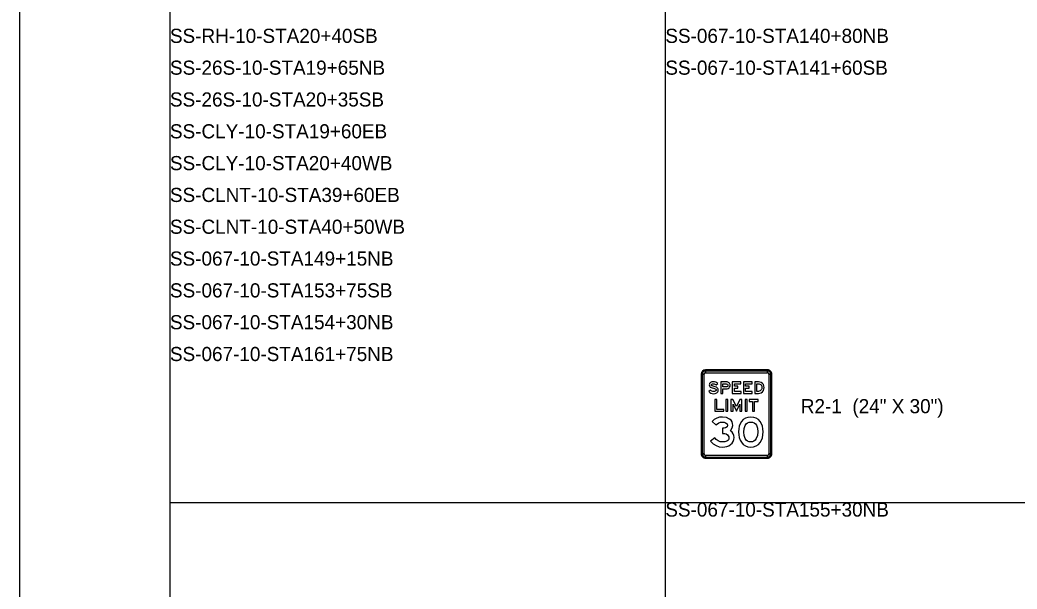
# Model space of a CAD drawing. Extents: x 1001568 to 1002149, y 1840825 to 1841423.
# Drawn here: x 1001886.41 to 1001914.59, y 1841079.02 to 1841095.12 of the extents above; entities that cross this region are included whole.
import ezdxf

# ---------------------------------------------------------------- set-up
doc = ezdxf.new("R2010")
doc.units = 0
for name, color, linetype in [('40', 7, 'Continuous'), ('R_No Plot', 7, 'Continuous'), ('SIGNS', 7, 'Continuous')]:
    doc.layers.add(name, color=color, linetype=linetype)

msp = doc.modelspace()

# ---------------------------------------------------------------- linework, layer by layer
at = {"layer": 'R_No Plot'}
for p, q in [((1001890.65, 1841110.667), (1001890.65, 1841048.127)), ((1001904.65, 1841110.667), (1001904.65, 1841048.127)), ((1001890.65, 1841081.469), (1001982.133, 1841081.469))]:
    msp.add_line(p, q, dxfattribs=at)
msp.add_lwpolyline([(1001886.411, 1841110.667), (1001964.232, 1841110.667), (1001964.232, 1841107.694), (1001968.454, 1841107.694), (1001968.454, 1841106.882), (1001982.133, 1841106.882), (1001982.133, 1841048.127), (1001886.411, 1841048.127)], close=True, dxfattribs=at)
at = {"layer": 'SIGNS'}
for p, q in [((1001905.662, 1841085.094), (1001905.662, 1841082.844)), ((1001905.693, 1841085.094), (1001905.745, 1841085.094)), ((1001907.537, 1841085.219), (1001905.787, 1841085.219)), ((1001905.787, 1841085.136), (1001905.787, 1841085.188)), ((1001907.537, 1841085.188), (1001907.537, 1841085.136)), ((1001907.578, 1841085.094), (1001907.63, 1841085.094)), ((1001907.662, 1841082.844), (1001907.662, 1841085.094)), ((1001905.745, 1841082.844), (1001905.693, 1841082.844)), ((1001905.787, 1841082.75), (1001905.787, 1841082.802)), ((1001905.787, 1841082.719), (1001907.537, 1841082.719)), ((1001907.537, 1841082.802), (1001907.537, 1841082.75)), ((1001907.63, 1841082.844), (1001907.578, 1841082.844))]:
    msp.add_line(p, q, dxfattribs=at)
for points in [[(1001905.693, 1841085.094), (1001905.693, 1841082.844), (1001905.745, 1841082.844), (1001905.745, 1841085.094), (1001905.693, 1841085.094), (1001905.693, 1841085.094)], [(1001907.537, 1841085.188), (1001905.787, 1841085.188), (1001905.787, 1841085.136), (1001907.537, 1841085.136), (1001907.537, 1841085.188), (1001907.537, 1841085.188)], [(1001907.63, 1841082.844), (1001907.63, 1841085.094), (1001907.578, 1841085.094), (1001907.578, 1841082.844), (1001907.63, 1841082.844), (1001907.63, 1841082.844)], [(1001905.878, 1841084.612), (1001905.907, 1841084.583), (1001905.939, 1841084.562), (1001905.975, 1841084.55), (1001906.015, 1841084.546), (1001906.061, 1841084.552), (1001906.102, 1841084.57), (1001906.121, 1841084.585), (1001906.134, 1841084.602), (1001906.142, 1841084.622), (1001906.145, 1841084.644), (1001906.142, 1841084.672), (1001906.133, 1841084.695), (1001906.117, 1841084.715), (1001906.095, 1841084.73), (1001906.063, 1841084.742), (1001906.002, 1841084.758), (1001905.98, 1841084.765), (1001905.965, 1841084.773), (1001905.955, 1841084.782), (1001905.952, 1841084.794), (1001905.955, 1841084.808), (1001905.966, 1841084.819), (1001905.983, 1841084.825), (1001906.007, 1841084.828), (1001906.029, 1841084.826), (1001906.05, 1841084.82), (1001906.069, 1841084.809), (1001906.086, 1841084.795), (1001906.13, 1841084.835), (1001906.104, 1841084.857), (1001906.076, 1841084.873), (1001906.044, 1841084.883), (1001906.009, 1841084.886), (1001905.966, 1841084.88), (1001905.93, 1841084.864), (1001905.914, 1841084.85), (1001905.902, 1841084.834), (1001905.895, 1841084.815), (1001905.893, 1841084.794), (1001905.896, 1841084.77), (1001905.905, 1841084.75), (1001905.921, 1841084.732), (1001905.943, 1841084.719), (1001906.036, 1841084.692), (1001906.058, 1841084.684), (1001906.073, 1841084.674), (1001906.083, 1841084.663), (1001906.086, 1841084.651), (1001906.084, 1841084.64), (1001906.079, 1841084.631), (1001906.071, 1841084.623), (1001906.06, 1841084.616), (1001906.038, 1841084.609), (1001906.014, 1841084.607), (1001905.988, 1841084.61), (1001905.965, 1841084.618), (1001905.944, 1841084.631), (1001905.926, 1841084.65)], [(1001906.542, 1841084.552), (1001906.789, 1841084.552), (1001906.789, 1841084.61), (1001906.602, 1841084.61), (1001906.602, 1841084.7), (1001906.701, 1841084.7), (1001906.701, 1841084.758), (1001906.602, 1841084.758), (1001906.602, 1841084.822), (1001906.783, 1841084.822), (1001906.783, 1841084.879), (1001906.542, 1841084.879)], [(1001906.858, 1841084.552), (1001907.106, 1841084.552), (1001907.106, 1841084.61), (1001906.918, 1841084.61), (1001906.918, 1841084.7), (1001907.017, 1841084.7), (1001907.017, 1841084.758), (1001906.918, 1841084.758), (1001906.918, 1841084.822), (1001907.1, 1841084.822), (1001907.1, 1841084.879), (1001906.858, 1841084.879)], [(1001906.052, 1841084.052), (1001906.299, 1841084.052), (1001906.299, 1841084.102), (1001906.11, 1841084.102), (1001906.11, 1841084.379), (1001906.052, 1841084.379)], [(1001906.358, 1841084.052), (1001906.418, 1841084.052), (1001906.418, 1841084.379), (1001906.358, 1841084.379)], [(1001906.505, 1841084.052), (1001906.563, 1841084.052), (1001906.563, 1841084.254), (1001906.659, 1841084.052), (1001906.757, 1841084.254), (1001906.757, 1841084.052), (1001906.815, 1841084.052), (1001906.815, 1841084.379), (1001906.757, 1841084.379), (1001906.659, 1841084.187), (1001906.562, 1841084.379), (1001906.505, 1841084.379)], [(1001906.905, 1841084.052), (1001906.964, 1841084.052), (1001906.964, 1841084.379), (1001906.905, 1841084.379)], [(1001907.116, 1841084.052), (1001907.174, 1841084.052), (1001907.174, 1841084.324), (1001907.269, 1841084.324), (1001907.269, 1841084.379), (1001907.022, 1841084.379), (1001907.022, 1841084.324), (1001907.116, 1841084.324)], [(1001905.928, 1841083.206), (1001906.002, 1841083.131), (1001906.084, 1841083.079), (1001906.172, 1841083.047), (1001906.268, 1841083.036), (1001906.33, 1841083.041), (1001906.388, 1841083.054), (1001906.441, 1841083.075), (1001906.491, 1841083.106), (1001906.537, 1841083.148), (1001906.57, 1841083.195), (1001906.589, 1841083.248), (1001906.596, 1841083.308), (1001906.589, 1841083.359), (1001906.57, 1841083.409), (1001906.537, 1841083.456), (1001906.491, 1841083.5), (1001906.541, 1841083.577), (1001906.558, 1841083.651), (1001906.552, 1841083.704), (1001906.535, 1841083.752), (1001906.506, 1841083.794), (1001906.466, 1841083.829), (1001906.375, 1841083.871), (1001906.265, 1841083.886), (1001906.181, 1841083.878), (1001906.103, 1841083.855), (1001906.032, 1841083.816), (1001905.969, 1841083.762), (1001906.079, 1841083.662), (1001906.12, 1841083.698), (1001906.164, 1841083.723), (1001906.211, 1841083.739), (1001906.262, 1841083.744), (1001906.311, 1841083.739), (1001906.354, 1841083.725), (1001906.394, 1841083.696), (1001906.407, 1841083.655), (1001906.394, 1841083.612), (1001906.355, 1841083.584), (1001906.312, 1841083.573), (1001906.262, 1841083.572), (1001906.262, 1841083.421), (1001906.283, 1841083.421), (1001906.332, 1841083.418), (1001906.373, 1841083.407), (1001906.406, 1841083.387), (1001906.43, 1841083.358), (1001906.443, 1841083.328), (1001906.448, 1841083.297), (1001906.444, 1841083.267), (1001906.432, 1841083.242), (1001906.412, 1841083.22), (1001906.385, 1841083.203), (1001906.331, 1841083.186), (1001906.266, 1841083.181), (1001906.203, 1841083.188), (1001906.143, 1841083.21), (1001906.089, 1841083.247), (1001906.048, 1841083.296)], [(1001905.787, 1841082.75), (1001907.537, 1841082.75), (1001907.537, 1841082.802), (1001905.787, 1841082.802), (1001905.787, 1841082.75), (1001905.787, 1841082.75)]]:
    msp.add_lwpolyline(points, close=True, dxfattribs=at)
for points in [[(1001906.215, 1841084.552), (1001906.273, 1841084.552), (1001906.273, 1841084.683), (1001906.368, 1841084.683), (1001906.4, 1841084.686), (1001906.428, 1841084.695), (1001906.45, 1841084.71), (1001906.468, 1841084.732), (1001906.478, 1841084.756), (1001906.482, 1841084.781), (1001906.48, 1841084.802), (1001906.474, 1841084.82), (1001906.465, 1841084.837), (1001906.451, 1841084.852), (1001906.435, 1841084.864), (1001906.417, 1841084.872), (1001906.397, 1841084.878), (1001906.375, 1841084.879), (1001906.215, 1841084.879), (1001906.215, 1841084.552)], [(1001906.273, 1841084.738), (1001906.273, 1841084.822), (1001906.37, 1841084.822), (1001906.389, 1841084.819), (1001906.405, 1841084.811), (1001906.416, 1841084.797), (1001906.42, 1841084.779), (1001906.417, 1841084.763), (1001906.406, 1841084.75), (1001906.391, 1841084.741), (1001906.373, 1841084.738), (1001906.273, 1841084.738)], [(1001907.175, 1841084.552), (1001907.282, 1841084.552), (1001907.323, 1841084.558), (1001907.361, 1841084.573), (1001907.396, 1841084.599), (1001907.422, 1841084.632), (1001907.437, 1841084.671), (1001907.442, 1841084.717), (1001907.437, 1841084.763), (1001907.422, 1841084.802), (1001907.397, 1841084.833), (1001907.362, 1841084.859), (1001907.324, 1841084.874), (1001907.286, 1841084.879), (1001907.175, 1841084.879), (1001907.175, 1841084.552)], [(1001907.233, 1841084.61), (1001907.233, 1841084.823), (1001907.28, 1841084.823), (1001907.302, 1841084.822), (1001907.321, 1841084.816), (1001907.339, 1841084.806), (1001907.354, 1841084.793), (1001907.365, 1841084.778), (1001907.373, 1841084.76), (1001907.378, 1841084.74), (1001907.38, 1841084.719), (1001907.377, 1841084.688), (1001907.369, 1841084.664), (1001907.353, 1841084.643), (1001907.328, 1841084.625), (1001907.303, 1841084.614), (1001907.28, 1841084.61), (1001907.233, 1841084.61)], [(1001907.412, 1841083.467), (1001907.407, 1841083.551), (1001907.392, 1841083.627), (1001907.366, 1841083.696), (1001907.331, 1841083.757), (1001907.279, 1841083.813), (1001907.218, 1841083.853), (1001907.147, 1841083.877), (1001907.067, 1841083.886), (1001906.986, 1841083.877), (1001906.915, 1841083.853), (1001906.854, 1841083.812), (1001906.802, 1841083.755), (1001906.766, 1841083.694), (1001906.74, 1841083.625), (1001906.725, 1841083.549), (1001906.72, 1841083.464), (1001906.725, 1841083.38), (1001906.74, 1841083.303), (1001906.765, 1841083.234), (1001906.8, 1841083.172), (1001906.851, 1841083.112), (1001906.912, 1841083.07), (1001906.982, 1841083.045), (1001907.062, 1841083.036), (1001907.145, 1841083.045), (1001907.217, 1841083.069), (1001907.28, 1841083.111), (1001907.331, 1841083.169), (1001907.366, 1841083.231), (1001907.392, 1841083.301), (1001907.407, 1841083.38), (1001907.412, 1841083.467)], [(1001907.264, 1841083.463), (1001907.253, 1841083.363), (1001907.22, 1841083.277), (1001907.191, 1841083.236), (1001907.155, 1841083.206), (1001907.114, 1841083.188), (1001907.067, 1841083.183), (1001907.017, 1841083.188), (1001906.974, 1841083.206), (1001906.938, 1841083.234), (1001906.908, 1841083.275), (1001906.876, 1841083.359), (1001906.865, 1841083.462), (1001906.876, 1841083.565), (1001906.908, 1841083.651), (1001906.939, 1841083.692), (1001906.975, 1841083.721), (1001907.018, 1841083.739), (1001907.067, 1841083.745), (1001907.117, 1841083.739), (1001907.16, 1841083.721), (1001907.196, 1841083.692), (1001907.225, 1841083.652), (1001907.254, 1841083.568), (1001907.264, 1841083.463)]]:
    msp.add_lwpolyline(points, dxfattribs=at)
for centre, radius, start, end in [((1001905.787, 1841085.094), 0.125, 90.0002, 179.9998), ((1001905.787, 1841085.094), 0.0937, 90.0002, 179.9998), ((1001905.787, 1841085.094), 0.0417, 90.0002, 179.9998), ((1001907.537, 1841085.094), 0.125, 0, 90.0002), ((1001907.537, 1841085.094), 0.0937, 0, 90.0002), ((1001907.537, 1841085.094), 0.0417, 0, 90.0002), ((1001905.787, 1841082.844), 0.125, 179.9998, 270.0001), ((1001905.787, 1841082.844), 0.0937, 179.9998, 270.0001), ((1001905.787, 1841082.844), 0.0417, 179.9998, 270.0001), ((1001907.537, 1841082.844), 0.125, 270.0001, 0.0003), ((1001907.537, 1841082.844), 0.0937, 270.0001, 0.0003), ((1001907.537, 1841082.844), 0.0417, 270.0001, 0.0003)]:
    msp.add_arc(centre, radius, start, end, dxfattribs=at)

# ---------------------------------------------------------------- texts
at = {"layer": '40'}
for s, p in [('SS-RH-10-STA20+40SB', (1001890.65, 1841094.469)), ('SS-067-10-STA140+80NB', (1001904.65, 1841094.469)), ('SS-26S-10-STA19+65NB', (1001890.65, 1841093.569)), ('SS-067-10-STA141+60SB', (1001904.65, 1841093.569)), ('SS-26S-10-STA20+35SB', (1001890.65, 1841092.669)), ('SS-CLY-10-STA19+60EB', (1001890.65, 1841091.769)), ('SS-CLY-10-STA20+40WB', (1001890.65, 1841090.869)), ('SS-CLNT-10-STA39+60EB', (1001890.65, 1841089.969)), ('SS-CLNT-10-STA40+50WB', (1001890.65, 1841089.069)), ('SS-067-10-STA149+15NB', (1001890.65, 1841088.169)), ('SS-067-10-STA153+75SB', (1001890.65, 1841087.269)), ('SS-067-10-STA154+30NB', (1001890.65, 1841086.369)), ('SS-067-10-STA161+75NB', (1001890.65, 1841085.469)), ('R2-1  (24" X 30")', (1001908.479, 1841083.993)), ('SS-067-10-STA155+30NB', (1001904.65, 1841081.069))]:
    msp.add_text(s, height=0.4, rotation=0, dxfattribs=at).set_placement(p)

doc.saveas('drawing.dxf')
